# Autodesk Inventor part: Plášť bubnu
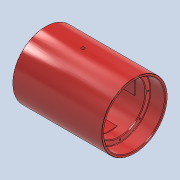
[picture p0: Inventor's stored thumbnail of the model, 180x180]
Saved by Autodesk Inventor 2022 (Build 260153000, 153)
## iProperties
Created: 2025-05
Part Number: Plášť bubnu
Material: Všeobecné
Document SubType Name: Modeling
Designer: jbart
Density: 1 g/cm^3
Appearance: Oranžovo-červená
Mass: 59094.3 g
Surface Area: 24781.8 cm^2
Volume: 59094.3 cm^3
Author: jbart
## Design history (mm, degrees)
sketch "Náčrt1"
  geometry: L1 (355, 190)-(265, 190); L2 (734, 270)-(0, 270); L3 (0, 0)-(714, 0); L4 (614, 150)-(355, 150); L5 (614, 250)-(614, 150); L6 (734, 250)-(614, 250); L7 (734, 270)-(734, 250); L8 (355, 150)-(355, 190); L9 (265, 190)-(265, 150); L10 (265, 150)-(80, 150); L11 (80, 150)-(80, 250); L12 (80, 250)-(0, 250); L13 (0, 250)-(0, 270); 5 further points
  constraints: 26 end point, 7 perpendicular, 2 horizontal, 2 horizontal alignment, 2 midpoint, 2 point on line, 2 vertical, 1 coincident, 1 vertical alignment
  dimensions: "d0" = 300 diameter of L4 L3; "d1" = 259 distance of L4.start L4.end; "d2" = 300 diameter of L10 L3; "d3" = 380 diameter of L1 L3; "d4" = 90 distance of L1.start L1.end; "d5" = 500 diameter of L6 L3; "d6" = 120 distance of L6.start L5.start; "d7" = 185 distance of L9.end L10.end; "d8" = 80 distance of L11.end L12.end; "d10" = 540 diameter of L2.start L3
revolve "Rotace1" sketch "Náčrt1" stored, may be unused: angle "d13" = 90 deg
sketch "Náčrt2" dims "d14" = 460
  geometry: L1 (0, 0)-(0, 230); 2 further points
  constraints: 2 coincident, 2 end point, 1 vertical, 1 vertical alignment, 2 other
hole "Díra1" sketch "Náčrt2" at (0, 230) diameter "d15" = 13.835; stored, may be unused: countersink angle "d19" = 90 deg, drill point angle "d21" = 118 deg; dims "d16" = 30, "d17" = 4, "d18" = 2, "d20" = 35
pattern_circular "Kruhové pole1" dims angle "d23" = 360 deg
sketch "Náčrt3" dims "d25" = 460
  geometry: L1 (0, 0)-(0, 230); 2 further points
  constraints: 2 coincident, 2 end point, 1 vertical, 1 vertical alignment, 2 other
hole "Díra2" sketch "Náčrt3" at (0, 230) diameter "d26" = 13.835; stored, may be unused: countersink angle "d30" = 90 deg, drill point angle "d32" = 118 deg; dims "d27" = 30, "d28" = 4, "d29" = 2, "d31" = 35
pattern_circular "Kruhové pole2" dims angle "d34" = 360 deg
chamfer "Zkosení1" distance "d36" = 5; stored, may be unused: second distance "d37" = 2, angle "d38" = 45 deg
fillet "Zaoblení1" dims "d39" = 4
chamfer "Zkosení2" distance "d40" = 2; stored, may be unused: second distance "d41" = 2, angle "d42" = 45 deg
node "Pracovní rovina1"
sketch "Náčrt4"
  geometry: L1 (57.411, 202)-(-57.411, 202); L2 (202, -57.411)-(202, 57.411); L3 (-57.411, -202)-(57.411, -202); L4 (-202, 57.411)-(-202, -57.411); L5 (0, 0)-(50, 0); L6 (50, 0)-(0, 0); L7 (0, 0)-(0, 50); C1 r 150 at (0, 0) reference; A1 r 210 centre (0, 0) between (-57.411, 202) and (-202, 57.411); A2 r 210 centre (0, 0) between (202, 57.411) and (57.411, 202); A3 r 210 centre (0, 0) between (57.411, -202) and (202, -57.411); A4 r 210 centre (0, 0) between (-202, -57.411) and (-57.411, -202); 2 further points
  constraints: 14 end point, 8 point on circle, 4 centre point, 2 parallel, 1 collinear, 1 horizontal, 1 perpendicular
  dimensions: "d43" = 210 radius of A2; "d44" = 404 distance between parallel lines of L4 L2; "d45" = 404 distance between parallel lines of L1 L3; "d46" = 202 distance from line of L2 point (0, 0); "d47" = 202 distance from line of L1 point (0, 0); "d48" = 50 distance of L5.start L5.end; "d49" = 50 distance of L5.start L7.end
node "Pracovní rovina2"
sketch "Náčrt5"
  geometry: L1 (63.246, 195)-(-63.246, 195); L2 (195, -63.246)-(195, 63.246); L3 (-63.246, -195)-(63.246, -195); L4 (-195, 63.246)-(-195, -63.246); L5 (0, 0)-(50, 0); L6 (0, 0)-(0, 50); C1 r 150 at (0, 0) reference; A1 r 205 centre (0, 0) between (-63.246, 195) and (-195, 63.246); A2 r 205 centre (0, 0) between (195, 63.246) and (63.246, 195); A3 r 205 centre (0, 0) between (63.246, -195) and (195, -63.246); A4 r 205 centre (0, 0) between (-195, -63.246) and (-63.246, -195); 2 further points
  constraints: 12 end point, 8 point on circle, 4 centre point, 1 horizontal, 1 vertical, 2 other
  dimensions: "d52" = 50 distance of L5.start L5.end; "d53" = 50 distance of L5.start L6.end; "d54" = 390 distance between parallel lines of L4 L2; "d55" = 390 distance between parallel lines of L3 L1
extrude "Vysunutí2" cut sketch "Náčrt5" distance "d56" = 150; taper "d57" = 0 deg
extrude "Vysunutí3" cut sketch "Náčrt4" distance "d59" = 180; taper "d60" = 0 deg
sketch "Náčrt6"
  geometry: C1 r 210 at (0, 0); 1 further point
  constraints: 1 centre point, 1 coincident
  dimensions: "d61" = 420 diameter of C1
extrude "Vysunutí4" cut sketch "Náčrt6" distance "d62" = 79; taper "d63" = 0 deg
sketch "Náčrt7"
  geometry: C1 r 205 at (0, 0); 1 further point
  constraints: 1 centre point, 1 coincident
  dimensions: "d65" = 410 diameter of C1
extrude "Vysunutí5" cut sketch "Náčrt7" distance "d66" = 35; taper "d67" = 0 deg
node "Pracovní rovina3"
sketch "Náčrt8"
  geometry: L1 (-734, -268)-(-734, 268) reference; 2 further points
  constraints: 1 horizontal alignment
  dimensions: "d69" = 424 distance from line of L1 point (-310, 0)
hole "Díra3" sketch "Náčrt8" at (-310, 0) diameter "d70" = 13.835; stored, may be unused: countersink angle "d74" = 90 deg, drill point angle "d76" = 118 deg; dims "d71" = 100, "d72" = 26, "d73" = 17, "d75" = 100
chamfer "Zkosení3" distance "d77" = 5; stored, may be unused: second distance "d78" = 2, angle "d79" = 45 deg
node "Těleso1"
other parameters: "d58" = -259, "d64" = -185
